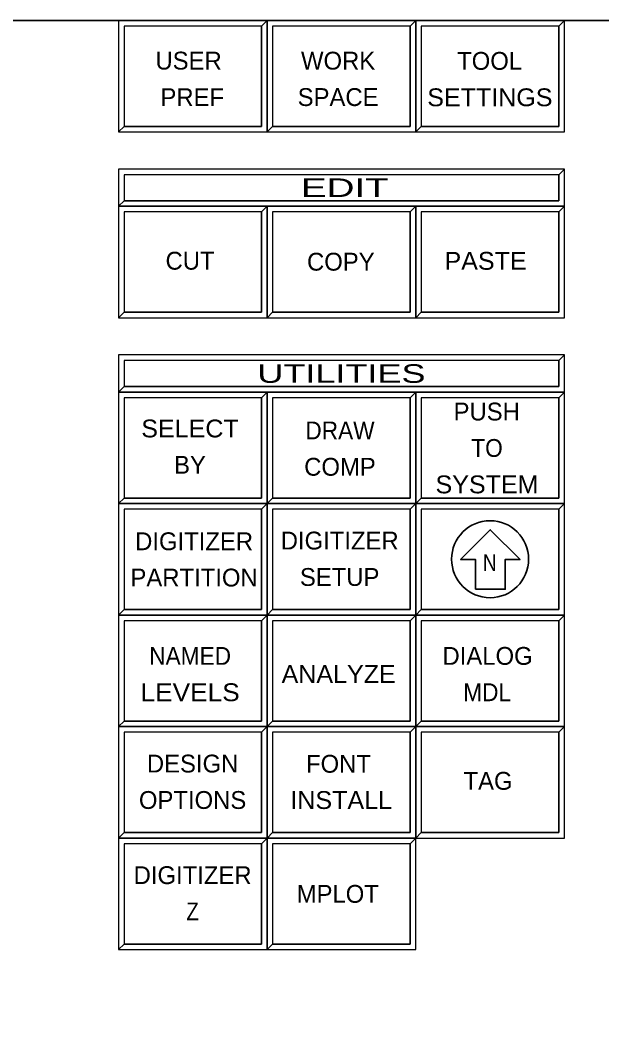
# Model space of a CAD drawing. Extents: x 95906.8 to 95923.6, y 90964.8 to 90972.8.
# Drawn here: x 95914.669 to 95916.232, y 90970.012 to 90972.762 of the extents above; entities that cross this region are included whole.
import ezdxf
from ezdxf.enums import TextEntityAlignment as Align

# ---------------------------------------------------------------- set-up
doc = ezdxf.new("R2010")
doc.units = 0
doc.header["$LTSCALE"] = 0.019
for name, color, linetype, lineweight in [('1', 7, 'Continuous', 25), ('11', 7, 'Continuous', 25), ('18', 7, 'Continuous', 25), ('2', 7, 'Continuous', 13), ('3', 7, 'Continuous', 25), ('6', 7, 'Continuous', 35), ('7', 7, 'Continuous', 35)]:
    doc.layers.add(name, color=color, linetype=linetype, lineweight=lineweight)

msp = doc.modelspace()

# ---------------------------------------------------------------- linework, layer by layer
at = {"layer": '1'}
for points in [[(95914.9323, 90972.4617), (95915.3323, 90972.4617), (95915.3323, 90972.7617), (95914.9323, 90972.7617)], [(95915.3323, 90972.4617), (95915.7323, 90972.4617), (95915.7323, 90972.7617), (95915.3323, 90972.7617)], [(95915.7323, 90972.4617), (95916.1323, 90972.4617), (95916.1323, 90972.7617), (95915.7323, 90972.7617)], [(95914.9323, 90972.2617), (95916.1323, 90972.2617), (95916.1323, 90972.3617), (95914.9323, 90972.3617)], [(95914.9323, 90971.9617), (95915.3323, 90971.9617), (95915.3323, 90972.2617), (95914.9323, 90972.2617)], [(95915.3323, 90971.9617), (95915.7323, 90971.9617), (95915.7323, 90972.2617), (95915.3323, 90972.2617)], [(95915.7323, 90971.9617), (95916.1323, 90971.9617), (95916.1323, 90972.2617), (95915.7323, 90972.2617)], [(95914.9323, 90971.7617), (95916.1323, 90971.7617), (95916.1323, 90971.8617), (95914.9323, 90971.8617)], [(95914.9323, 90971.4617), (95915.3323, 90971.4617), (95915.3323, 90971.7617), (95914.9323, 90971.7617)], [(95915.3323, 90971.4617), (95915.7323, 90971.4617), (95915.7323, 90971.7617), (95915.3323, 90971.7617)], [(95915.7323, 90971.4617), (95916.1323, 90971.4617), (95916.1323, 90971.7617), (95915.7323, 90971.7617)], [(95914.9323, 90971.1617), (95915.3323, 90971.1617), (95915.3323, 90971.4617), (95914.9323, 90971.4617)], [(95915.3323, 90971.1617), (95915.7323, 90971.1617), (95915.7323, 90971.4617), (95915.3323, 90971.4617)], [(95915.7323, 90971.1617), (95916.1323, 90971.1617), (95916.1323, 90971.4617), (95915.7323, 90971.4617)], [(95914.9323, 90970.8617), (95915.3323, 90970.8617), (95915.3323, 90971.1617), (95914.9323, 90971.1617)], [(95915.3323, 90970.8617), (95915.7323, 90970.8617), (95915.7323, 90971.1617), (95915.3323, 90971.1617)], [(95915.7323, 90970.8617), (95916.1323, 90970.8617), (95916.1323, 90971.1617), (95915.7323, 90971.1617)], [(95914.9323, 90970.5617), (95915.3323, 90970.5617), (95915.3323, 90970.8617), (95914.9323, 90970.8617)], [(95915.3323, 90970.5617), (95915.7323, 90970.5617), (95915.7323, 90970.8617), (95915.3323, 90970.8617)], [(95915.7323, 90970.5617), (95916.1323, 90970.5617), (95916.1323, 90970.8617), (95915.7323, 90970.8617)], [(95914.9323, 90970.2617), (95915.3323, 90970.2617), (95915.3323, 90970.5617), (95914.9323, 90970.5617)], [(95915.3323, 90970.2617), (95915.7323, 90970.2617), (95915.7323, 90970.5617), (95915.3323, 90970.5617)]]:
    msp.add_lwpolyline(points, close=True, dxfattribs=at)
at = {"layer": '11'}
for points in [[(95914.9473, 90972.4767), (95915.3173, 90972.4767), (95915.3173, 90972.7467), (95914.9473, 90972.7467)], [(95915.3473, 90972.4767), (95915.7173, 90972.4767), (95915.7173, 90972.7467), (95915.3473, 90972.7467)], [(95915.7473, 90972.4767), (95916.1173, 90972.4767), (95916.1173, 90972.7467), (95915.7473, 90972.7467)], [(95914.9473, 90971.9767), (95915.3173, 90971.9767), (95915.3173, 90972.2467), (95914.9473, 90972.2467)], [(95915.3473, 90971.9767), (95915.7173, 90971.9767), (95915.7173, 90972.2467), (95915.3473, 90972.2467)], [(95915.7473, 90971.9767), (95916.1173, 90971.9767), (95916.1173, 90972.2467), (95915.7473, 90972.2467)], [(95914.9473, 90971.4767), (95915.3173, 90971.4767), (95915.3173, 90971.7467), (95914.9473, 90971.7467)], [(95915.3473, 90971.4767), (95915.7173, 90971.4767), (95915.7173, 90971.7467), (95915.3473, 90971.7467)], [(95915.7473, 90971.4767), (95916.1173, 90971.4767), (95916.1173, 90971.7467), (95915.7473, 90971.7467)], [(95914.9473, 90971.1767), (95915.3173, 90971.1767), (95915.3173, 90971.4467), (95914.9473, 90971.4467)], [(95915.3473, 90971.1767), (95915.7173, 90971.1767), (95915.7173, 90971.4467), (95915.3473, 90971.4467)], [(95915.7473, 90971.1767), (95916.1173, 90971.1767), (95916.1173, 90971.4467), (95915.7473, 90971.4467)], [(95914.9473, 90970.8767), (95915.3173, 90970.8767), (95915.3173, 90971.1467), (95914.9473, 90971.1467)], [(95915.3473, 90970.8767), (95915.7173, 90970.8767), (95915.7173, 90971.1467), (95915.3473, 90971.1467)], [(95915.7473, 90970.8767), (95916.1173, 90970.8767), (95916.1173, 90971.1467), (95915.7473, 90971.1467)], [(95914.9473, 90970.5767), (95915.3173, 90970.5767), (95915.3173, 90970.8467), (95914.9473, 90970.8467)], [(95915.3473, 90970.5767), (95915.7173, 90970.5767), (95915.7173, 90970.8467), (95915.3473, 90970.8467)], [(95915.7473, 90970.5767), (95916.1173, 90970.5767), (95916.1173, 90970.8467), (95915.7473, 90970.8467)], [(95914.9473, 90970.2767), (95915.3173, 90970.2767), (95915.3173, 90970.5467), (95914.9473, 90970.5467)], [(95915.3473, 90970.2767), (95915.7173, 90970.2767), (95915.7173, 90970.5467), (95915.3473, 90970.5467)]]:
    msp.add_lwpolyline(points, close=True, dxfattribs=at)
at = {"layer": '18'}
for points in [[(95914.9473, 90972.2767), (95916.1173, 90972.2767), (95916.1173, 90972.3467), (95914.9473, 90972.3467)], [(95914.9473, 90971.7767), (95916.1173, 90971.7767), (95916.1173, 90971.8467), (95914.9473, 90971.8467)]]:
    msp.add_lwpolyline(points, close=True, dxfattribs=at)
at = {"layer": '2'}
for points in [[(95914.9323, 90972.7617), (95914.9323, 90972.4617), (95914.9473, 90972.4767), (95914.9473, 90972.7467), (95915.3173, 90972.7467), (95915.3323, 90972.7617)], [(95915.3323, 90972.7617), (95915.3323, 90972.4617), (95915.3473, 90972.4767), (95915.3473, 90972.7467), (95915.7173, 90972.7467), (95915.7323, 90972.7617)], [(95915.7323, 90972.7617), (95915.7323, 90972.4617), (95915.7473, 90972.4767), (95915.7473, 90972.7467), (95916.1173, 90972.7467), (95916.1323, 90972.7617)], [(95914.9323, 90972.3617), (95914.9323, 90972.2617), (95914.9473, 90972.2767), (95914.9473, 90972.3467), (95916.1173, 90972.3467), (95916.1323, 90972.3617)], [(95914.9323, 90972.2617), (95914.9323, 90971.9617), (95914.9473, 90971.9767), (95914.9473, 90972.2467), (95915.3173, 90972.2467), (95915.3323, 90972.2617)], [(95915.3323, 90972.2617), (95915.3323, 90971.9617), (95915.3473, 90971.9767), (95915.3473, 90972.2467), (95915.7173, 90972.2467), (95915.7323, 90972.2617)], [(95915.7323, 90972.2617), (95915.7323, 90971.9617), (95915.7473, 90971.9767), (95915.7473, 90972.2467), (95916.1173, 90972.2467), (95916.1323, 90972.2617)], [(95914.9323, 90971.8617), (95914.9323, 90971.7617), (95914.9473, 90971.7767), (95914.9473, 90971.8467), (95916.1173, 90971.8467), (95916.1323, 90971.8617)], [(95914.9323, 90971.7617), (95914.9323, 90971.4617), (95914.9473, 90971.4767), (95914.9473, 90971.7467), (95915.3173, 90971.7467), (95915.3323, 90971.7617)], [(95915.3323, 90971.7617), (95915.3323, 90971.4617), (95915.3473, 90971.4767), (95915.3473, 90971.7467), (95915.7173, 90971.7467), (95915.7323, 90971.7617)], [(95915.7323, 90971.7617), (95915.7323, 90971.4617), (95915.7473, 90971.4767), (95915.7473, 90971.7467), (95916.1173, 90971.7467), (95916.1323, 90971.7617)], [(95914.9323, 90971.4617), (95914.9323, 90971.1617), (95914.9473, 90971.1767), (95914.9473, 90971.4467), (95915.3173, 90971.4467), (95915.3323, 90971.4617)], [(95915.3323, 90971.4617), (95915.3323, 90971.1617), (95915.3473, 90971.1767), (95915.3473, 90971.4467), (95915.7173, 90971.4467), (95915.7323, 90971.4617)], [(95915.7323, 90971.4617), (95915.7323, 90971.1617), (95915.7473, 90971.1767), (95915.7473, 90971.4467), (95916.1173, 90971.4467), (95916.1323, 90971.4617)], [(95914.9323, 90971.1617), (95914.9323, 90970.8617), (95914.9473, 90970.8767), (95914.9473, 90971.1467), (95915.3173, 90971.1467), (95915.3323, 90971.1617)], [(95915.3323, 90971.1617), (95915.3323, 90970.8617), (95915.3473, 90970.8767), (95915.3473, 90971.1467), (95915.7173, 90971.1467), (95915.7323, 90971.1617)], [(95915.7323, 90971.1617), (95915.7323, 90970.8617), (95915.7473, 90970.8767), (95915.7473, 90971.1467), (95916.1173, 90971.1467), (95916.1323, 90971.1617)], [(95914.9323, 90970.8617), (95914.9323, 90970.5617), (95914.9473, 90970.5767), (95914.9473, 90970.8467), (95915.3173, 90970.8467), (95915.3323, 90970.8617)], [(95915.3323, 90970.8617), (95915.3323, 90970.5617), (95915.3473, 90970.5767), (95915.3473, 90970.8467), (95915.7173, 90970.8467), (95915.7323, 90970.8617)], [(95915.7323, 90970.8617), (95915.7323, 90970.5617), (95915.7473, 90970.5767), (95915.7473, 90970.8467), (95916.1173, 90970.8467), (95916.1323, 90970.8617)], [(95914.9323, 90970.5617), (95914.9323, 90970.2617), (95914.9473, 90970.2767), (95914.9473, 90970.5467), (95915.3173, 90970.5467), (95915.3323, 90970.5617)], [(95915.3323, 90970.5617), (95915.3323, 90970.2617), (95915.3473, 90970.2767), (95915.3473, 90970.5467), (95915.7173, 90970.5467), (95915.7323, 90970.5617)]]:
    msp.add_lwpolyline(points, close=True, dxfattribs=at)
at = {"layer": '3'}
for points in [[(95914.9323, 90972.4617), (95915.3323, 90972.4617), (95915.3323, 90972.7617), (95915.3173, 90972.7467), (95915.3173, 90972.4767), (95914.9473, 90972.4767)], [(95915.3323, 90972.4617), (95915.7323, 90972.4617), (95915.7323, 90972.7617), (95915.7173, 90972.7467), (95915.7173, 90972.4767), (95915.3473, 90972.4767)], [(95915.7323, 90972.4617), (95916.1323, 90972.4617), (95916.1323, 90972.7617), (95916.1173, 90972.7467), (95916.1173, 90972.4767), (95915.7473, 90972.4767)], [(95914.9323, 90972.2617), (95916.1323, 90972.2617), (95916.1323, 90972.3617), (95916.1173, 90972.3467), (95916.1173, 90972.2767), (95914.9473, 90972.2767)], [(95914.9323, 90971.9617), (95915.3323, 90971.9617), (95915.3323, 90972.2617), (95915.3173, 90972.2467), (95915.3173, 90971.9767), (95914.9473, 90971.9767)], [(95915.3323, 90971.9617), (95915.7323, 90971.9617), (95915.7323, 90972.2617), (95915.7173, 90972.2467), (95915.7173, 90971.9767), (95915.3473, 90971.9767)], [(95915.7323, 90971.9617), (95916.1323, 90971.9617), (95916.1323, 90972.2617), (95916.1173, 90972.2467), (95916.1173, 90971.9767), (95915.7473, 90971.9767)], [(95914.9323, 90971.7617), (95916.1323, 90971.7617), (95916.1323, 90971.8617), (95916.1173, 90971.8467), (95916.1173, 90971.7767), (95914.9473, 90971.7767)], [(95914.9323, 90971.4617), (95915.3323, 90971.4617), (95915.3323, 90971.7617), (95915.3173, 90971.7467), (95915.3173, 90971.4767), (95914.9473, 90971.4767)], [(95915.3323, 90971.4617), (95915.7323, 90971.4617), (95915.7323, 90971.7617), (95915.7173, 90971.7467), (95915.7173, 90971.4767), (95915.3473, 90971.4767)], [(95915.7323, 90971.4617), (95916.1323, 90971.4617), (95916.1323, 90971.7617), (95916.1173, 90971.7467), (95916.1173, 90971.4767), (95915.7473, 90971.4767)], [(95914.9323, 90971.1617), (95915.3323, 90971.1617), (95915.3323, 90971.4617), (95915.3173, 90971.4467), (95915.3173, 90971.1767), (95914.9473, 90971.1767)], [(95915.3323, 90971.1617), (95915.7323, 90971.1617), (95915.7323, 90971.4617), (95915.7173, 90971.4467), (95915.7173, 90971.1767), (95915.3473, 90971.1767)], [(95915.7323, 90971.1617), (95916.1323, 90971.1617), (95916.1323, 90971.4617), (95916.1173, 90971.4467), (95916.1173, 90971.1767), (95915.7473, 90971.1767)], [(95914.9323, 90970.8617), (95915.3323, 90970.8617), (95915.3323, 90971.1617), (95915.3173, 90971.1467), (95915.3173, 90970.8767), (95914.9473, 90970.8767)], [(95915.3323, 90970.8617), (95915.7323, 90970.8617), (95915.7323, 90971.1617), (95915.7173, 90971.1467), (95915.7173, 90970.8767), (95915.3473, 90970.8767)], [(95915.7323, 90970.8617), (95916.1323, 90970.8617), (95916.1323, 90971.1617), (95916.1173, 90971.1467), (95916.1173, 90970.8767), (95915.7473, 90970.8767)], [(95914.9323, 90970.5617), (95915.3323, 90970.5617), (95915.3323, 90970.8617), (95915.3173, 90970.8467), (95915.3173, 90970.5767), (95914.9473, 90970.5767)], [(95915.3323, 90970.5617), (95915.7323, 90970.5617), (95915.7323, 90970.8617), (95915.7173, 90970.8467), (95915.7173, 90970.5767), (95915.3473, 90970.5767)], [(95915.7323, 90970.5617), (95916.1323, 90970.5617), (95916.1323, 90970.8617), (95916.1173, 90970.8467), (95916.1173, 90970.5767), (95915.7473, 90970.5767)], [(95914.9323, 90970.2617), (95915.3323, 90970.2617), (95915.3323, 90970.5617), (95915.3173, 90970.5467), (95915.3173, 90970.2767), (95914.9473, 90970.2767)], [(95915.3323, 90970.2617), (95915.7323, 90970.2617), (95915.7323, 90970.5617), (95915.7173, 90970.5467), (95915.7173, 90970.2767), (95915.3473, 90970.2767)]]:
    msp.add_lwpolyline(points, close=True, dxfattribs=at)
at = {"layer": '6'}
msp.add_lwpolyline([(95915.893, 90971.2314), (95915.893, 90971.3114), (95915.853, 90971.3114), (95915.933, 90971.3914), (95916.013, 90971.3114), (95915.973, 90971.3114), (95915.973, 90971.2314)], close=True, dxfattribs=at)
msp.add_circle((95915.9323, 90971.3122), 0.1036, dxfattribs=at)
at = {"layer": '7'}
msp.add_lwpolyline([(95906.8323, 90972.7617), (95918.8323, 90972.7617), (95918.8323, 90964.7617), (95906.8323, 90964.7617)], close=True, dxfattribs=at)

# ---------------------------------------------------------------- texts
at = {"layer": '6'}
for s, p in [('USER', (95915.1211, 90972.6296)), ('WORK', (95915.5234, 90972.6295)), ('TOOL', (95915.9311, 90972.6289)), ('PREF', (95915.131, 90972.5313)), ('SPACE', (95915.5234, 90972.5315)), ('CUT', (95915.125, 90972.0912)), ('COPY', (95915.5307, 90972.0886)), ('PUSH', (95915.9233, 90971.6854)), ('BY', (95915.1248, 90971.5421)), ('COMP', (95915.5284, 90971.5368)), ('DIGITIZER', (95915.1359, 90971.3364)), ('DIGITIZER', (95915.5277, 90971.3383)), ('PARTITION', (95915.1359, 90971.2388)), ('SETUP', (95915.5276, 90971.2403)), ('DIALOG', (95915.9256, 90971.028)), ('DESIGN', (95915.1319, 90970.7383)), ('FONT', (95915.5244, 90970.7377)), ('TAG', (95915.9268, 90970.6918)), ('OPTIONS', (95915.1319, 90970.6403)), ('DIGITIZER', (95915.1319, 90970.4381)), ('MPLOT', (95915.5225, 90970.3877))]:
    msp.add_text(s, height=0.048, dxfattribs=at).set_placement(p, align=Align.CENTER)
for s, height, width, p in [('SETTINGS', 0.048, 1.05, (95915.9318, 90972.5309)), ('PASTE', 0.048, 1.05, (95915.9202, 90972.0909)), ('SELECT', 0.048, 1.05, (95915.1249, 90971.6399)), ('DRAW', 0.048, 0.95, (95915.5284, 90971.6346)), ('TO', 0.048, 0.95, (95915.9241, 90971.5874)), ('SYSTEM', 0.048, 1.05, (95915.9241, 90971.4894)), ('N', 0.045, 0.85, (95915.9315, 90971.2804)), ('NAMED', 0.048, 0.95, (95915.1252, 90971.028)), ('ANALYZE', 0.048, 1.05, (95915.5249, 90970.9791)), ('LEVELS', 0.048, 1.1, (95915.1252, 90970.9302)), ('MDL', 0.048, 0.95, (95915.9244, 90970.9302)), ('INSTALL', 0.048, 1.05, (95915.5317, 90970.6402)), ('Z', 0.048, 0.85, (95915.1319, 90970.3405))]:
    msp.add_text(s, height=height, dxfattribs=dict(at, width=width)).set_placement(p, align=Align.CENTER)
at = {"layer": '7'}
for s, height, width, p in [('       EDIT       ', 0.05, 1.55, (95915.5415, 90972.2867)), ('       UTILITIES       ', 0.04999, 1.45, (95915.5323, 90971.7867))]:
    msp.add_text(s, height=height, dxfattribs=dict(at, width=width)).set_placement(p, align=Align.CENTER)

doc.saveas('drawing.dxf')
